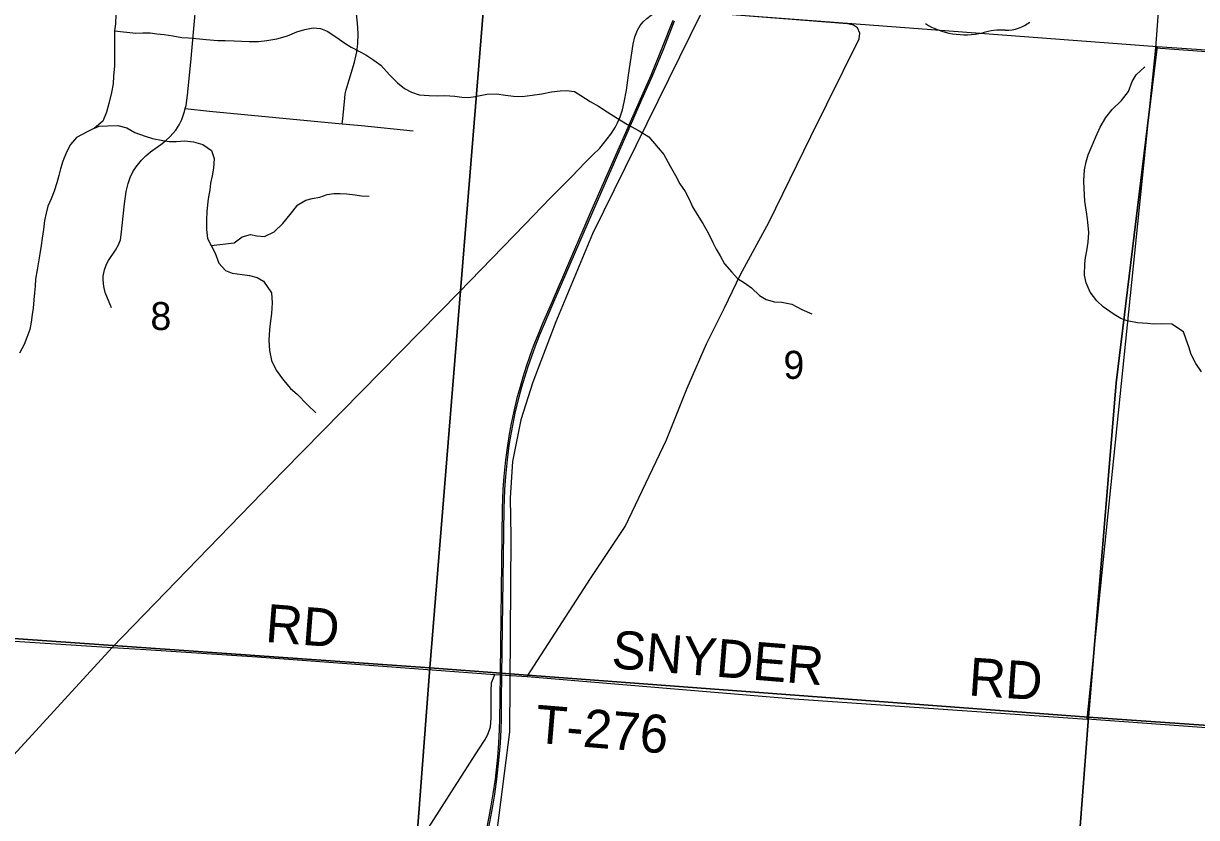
# Model space of a CAD drawing. Extents: x 0 to 42.5, y 0 to 22.
# Drawn here: x 2.796 to 3.672, y 14.84 to 15.433 of the extents above; entities that cross this region are included whole.
import ezdxf

# ---------------------------------------------------------------- set-up
doc = ezdxf.new("R2010")
doc.units = 0
for name, color, linetype in [('GM_X_County_Road', 7, 'Continuous'), ('GM_X_Minor_River', 7, 'Continuous'), ('GM_X_Rail_Line', 7, 'Continuous'), ('GM_X_Section', 7, 'Continuous'), ('GM_X_Section_Text', 7, 'Continuous'), ('GM_X_State_Route', 7, 'Continuous'), ('GM_X_State_Shield', 7, 'Continuous'), ('GM_X_Township_Road', 7, 'Continuous'), ('GM_X_Township_Road_Text', 7, 'Continuous')]:
    doc.layers.add(name, color=color, linetype=linetype)

msp = doc.modelspace()

# ---------------------------------------------------------------- linework, layer by layer
at = {"layer": 'GM_X_County_Road'}
msp.add_lwpolyline([(3.81125, 14.38966), (3.84476, 14.85241), (3.84714, 14.88263), (3.84662, 14.88758), (3.84418, 14.89065), (3.84154, 14.89333), (3.83908, 14.89469), (3.82959, 14.89592), (3.58977, 14.91333), (3.64105, 15.41464), (3.65438, 15.5918)], dxfattribs=at)
at = {"layer": 'GM_X_Minor_River'}
for points in [[(2.86473, 15.43941), (2.86453, 15.43257), (2.86376, 15.42744), (2.86371, 15.40122), (2.86313, 15.39343), (2.86274, 15.38773), (2.86159, 15.38127), (2.85968, 15.37311), (2.85796, 15.36665), (2.8551, 15.35982), (2.84882, 15.3547), (2.84388, 15.35204), (2.83533, 15.34769), (2.83095, 15.34238), (2.82791, 15.33668), (2.82524, 15.33004), (2.82352, 15.32434), (2.82218, 15.31921), (2.82084, 15.31389), (2.81874, 15.30763), (2.81645, 15.30174)], [(2.86376, 15.42744), (2.87971, 15.4257), (2.88484, 15.42588), (2.89053, 15.42587), (2.89547, 15.42511), (2.90078, 15.42453), (2.90724, 15.42357), (2.91407, 15.42241), (2.91901, 15.42203), (2.92737, 15.42125), (2.9323, 15.42086), (2.94085, 15.42009), (2.94654, 15.42008), (2.95319, 15.41988), (2.9587, 15.41949), (2.96439, 15.41929), (2.97123, 15.41947), (2.9775, 15.42003), (2.9851, 15.42134), (2.99289, 15.42361), (2.99992, 15.42664), (3.006, 15.42834), (3.01208, 15.42966), (3.01758, 15.42908), (3.02252, 15.42698), (3.02897, 15.42279), (3.03579, 15.41803), (3.04054, 15.41517), (3.04661, 15.41193), (3.05135, 15.40945), (3.05742, 15.40545), (3.06254, 15.40164), (3.06918, 15.39441), (3.07505, 15.38851), (3.08036, 15.38413), (3.08549, 15.38146), (3.09118, 15.37955), (3.09878, 15.37897), (3.10523, 15.37877), (3.11036, 15.37895), (3.11777, 15.37856), (3.12308, 15.37779), (3.12821, 15.37759), (3.13315, 15.37834), (3.1417, 15.38003), (3.14891, 15.38021), (3.15575, 15.37925), (3.16163, 15.37848), (3.16809, 15.37828), (3.17569, 15.37922), (3.1829, 15.38015), (3.19012, 15.38166), (3.19639, 15.3826), (3.20133, 15.38278), (3.20721, 15.38201), (3.21196, 15.37896), (3.21898, 15.37458), (3.22505, 15.37096), (3.23169, 15.36677), (3.23908, 15.36201), (3.24667, 15.35743), (3.2554, 15.35267), (3.26261, 15.3481), (3.26962, 15.33991), (3.27379, 15.33497), (3.27852, 15.32622), (3.2825, 15.31937), (3.28591, 15.3131), (3.2897, 15.30739), (3.29272, 15.30168), (3.29518, 15.29579), (3.29878, 15.29008), (3.30295, 15.28343), (3.30693, 15.27639), (3.31052, 15.26916), (3.31298, 15.26422), (3.31582, 15.25927), (3.31904, 15.25319), (3.32454, 15.2471), (3.3289, 15.24234), (3.33402, 15.2391), (3.33933, 15.23529), (3.34521, 15.22977), (3.35033, 15.22672), (3.3564, 15.22481), (3.36191, 15.2248), (3.36931, 15.22308), (3.3769, 15.21927), (3.3843, 15.21602)], [(3.62348, 15.38945), (3.62653, 15.39458), (3.633, 15.40046)], [(3.67515, 15.17257), (3.67099, 15.17885), (3.66739, 15.18551), (3.66569, 15.1914), (3.6638, 15.19672), (3.66172, 15.20262), (3.65318, 15.20814), (3.64559, 15.20854), (3.6397, 15.20836), (3.63496, 15.20875), (3.62736, 15.20914), (3.61977, 15.21067), (3.61502, 15.21258), (3.61009, 15.21544), (3.60193, 15.22115), (3.59719, 15.22572), (3.59208, 15.23219), (3.58924, 15.23903), (3.58792, 15.24474), (3.58813, 15.25329), (3.5887, 15.25804), (3.58966, 15.26297), (3.59062, 15.26943), (3.5912, 15.27665), (3.59027, 15.28444), (3.58952, 15.29052), (3.58801, 15.30022), (3.58765, 15.30953), (3.58747, 15.31523), (3.58786, 15.3234), (3.5892, 15.32947), (3.59073, 15.3346), (3.59283, 15.33992), (3.59626, 15.34827), (3.5995, 15.35549), (3.60369, 15.3627), (3.60864, 15.36858), (3.61548, 15.37541), (3.62062, 15.38205), (3.62348, 15.38945)], [(2.84882, 15.3547), (2.85225, 15.35621), (2.85851, 15.35639), (2.8663, 15.35657), (2.87313, 15.35485), (2.87901, 15.35142), (2.88661, 15.34874), (2.8923, 15.34683), (2.89989, 15.34549), (2.90483, 15.34472), (2.90977, 15.34471), (2.91641, 15.34508), (2.92268, 15.34431), (2.9297, 15.3424), (2.93615, 15.33783), (2.93823, 15.33193), (2.93765, 15.32471), (2.93669, 15.31902), (2.93554, 15.31351), (2.93496, 15.30857), (2.93362, 15.30173), (2.93266, 15.29261), (2.93246, 15.28577), (2.93245, 15.27894), (2.93319, 15.27228), (2.93603, 15.26696), (2.93887, 15.26125), (2.94171, 15.25384), (2.94664, 15.24832), (2.95176, 15.24641), (2.95917, 15.24526), (2.96448, 15.24468), (2.97037, 15.24315), (2.97511, 15.24029), (2.98098, 15.23173), (2.98154, 15.22413), (2.98096, 15.21615), (2.97999, 15.20874), (2.97942, 15.204), (2.97902, 15.19621), (2.97958, 15.1886), (2.98109, 15.18119), (2.98449, 15.17397), (2.98999, 15.16655), (2.9953, 15.16008), (3.00023, 15.15589), (3.008, 15.1479), (3.01407, 15.142)], [(2.81645, 15.30174), (2.81417, 15.29643), (2.81283, 15.29111), (2.81168, 15.28579), (2.81072, 15.27895), (2.80976, 15.2725), (2.80899, 15.26699), (2.80803, 15.26072), (2.80707, 15.25483), (2.80611, 15.24875), (2.80496, 15.24191), (2.80457, 15.23659), (2.80418, 15.23166), (2.8036, 15.22634), (2.80302, 15.22026), (2.80226, 15.21551), (2.80168, 15.20962), (2.80053, 15.2043), (2.79843, 15.19823), (2.79633, 15.1931), (2.7929, 15.18665)], [(2.93603, 15.26696), (2.95313, 15.26902), (2.95902, 15.27357), (2.96529, 15.27527), (2.97004, 15.27431), (2.97573, 15.27373), (2.98296, 15.27714), (2.98942, 15.2834), (2.99494, 15.29023), (3.00065, 15.29744), (3.00673, 15.30085), (3.01148, 15.30198), (3.01699, 15.30311), (3.0225, 15.305), (3.02744, 15.30575), (3.03219, 15.30593), (3.03712, 15.30555), (3.04339, 15.30496), (3.04814, 15.3042), (3.05383, 15.30381)]]:
    msp.add_lwpolyline(points, dxfattribs=at)
at = {"layer": 'GM_X_Rail_Line'}
for points in [[(3.47328, 15.92052), (3.46744, 15.82178), (3.46367, 15.75338), (3.44096, 15.69989), (3.43137, 15.67586), (3.41647, 15.65133), (3.3017, 15.44053), (3.22062, 15.27562), (3.19329, 15.2099), (3.17616, 15.16485), (3.16703, 15.1369), (3.161, 15.10576), (3.15922, 15.07853), (3.15956, 15.04953), (3.15856, 14.90389), (3.14925, 14.82993)], [(3.14195, 14.83262), (3.14349, 14.84043), (3.14503, 14.84859), (3.1465, 14.85754), (3.1481, 14.86856), (3.14988, 14.88491), (3.15063, 14.8954), (3.15118, 14.90554), (3.15138, 14.91343), (3.15161, 14.92814), (3.15338, 15.07069), (3.15386, 15.08489), (3.15462, 15.09455), (3.15586, 15.10703), (3.15731, 15.11772), (3.15869, 15.12621), (3.1602, 15.13413), (3.16179, 15.14199), (3.16469, 15.1542), (3.16676, 15.16165), (3.16889, 15.16903), (3.17138, 15.17689), (3.17413, 15.18482), (3.17689, 15.19247), (3.18, 15.20034), (3.18358, 15.20888), (3.18997, 15.22366), (3.21974, 15.29254), (3.25644, 15.3764), (3.26434, 15.39419), (3.27265, 15.41458), (3.28083, 15.4352)], [(3.14313, 14.83237), (3.14467, 14.84021), (3.14621, 14.84838), (3.14768, 14.85736), (3.14929, 14.86841), (3.15107, 14.88481), (3.15183, 14.89532), (3.15238, 14.9055), (3.15258, 14.9134), (3.15281, 14.92812), (3.15458, 15.07067), (3.15506, 15.08483), (3.15581, 15.09445), (3.15705, 15.10689), (3.1585, 15.11754), (3.15987, 15.126), (3.16138, 15.1339), (3.16296, 15.14174), (3.16585, 15.1539), (3.16791, 15.16133), (3.17004, 15.16868), (3.17252, 15.17652), (3.17527, 15.18442), (3.17802, 15.19205), (3.18111, 15.19989), (3.18468, 15.20841), (3.19108, 15.22319), (3.22084, 15.29206), (3.25754, 15.37592), (3.26545, 15.39372), (3.27376, 15.41413), (3.28194, 15.43475)]]:
    msp.add_lwpolyline(points, dxfattribs=at)
at = {"layer": 'GM_X_Section'}
for points in [[(2.62095, 15.50275), (3.14004, 15.45367), (3.09918, 14.95159), (2.58723, 14.98757)], [(3.14004, 15.45367), (3.64215, 15.41565), (3.61158, 15.16447), (3.59088, 14.91475), (3.09918, 14.95159)], [(3.64215, 15.41565), (4.14371, 15.38143), (4.10606, 14.87895), (3.59088, 14.91475), (3.61158, 15.16447)], [(2.58723, 14.98757), (3.09918, 14.95159), (3.06197, 14.45953), (2.55405, 14.50856)], [(3.09918, 14.95159), (3.59088, 14.91475), (3.55348, 14.42497), (3.06197, 14.45953)], [(3.59088, 14.91475), (4.10606, 14.87895), (4.07019, 14.38934), (3.55348, 14.42497)]]:
    msp.add_lwpolyline(points, close=True, dxfattribs=at)
at = {"layer": 'GM_X_State_Route'}
for points in [[(3.22092, 15.33472), (3.22599, 15.33968), (3.23429, 15.35011), (3.23748, 15.35522), (3.23929, 15.35873), (3.24132, 15.3631), (3.24291, 15.36821), (3.2443, 15.37406), (3.24589, 15.38289), (3.24749, 15.39418), (3.251, 15.41738), (3.25217, 15.42291), (3.25409, 15.4277), (3.25632, 15.43121), (3.25835, 15.43409), (3.26111, 15.43643), (3.26452, 15.43898), (3.26899, 15.4409), (3.27261, 15.44218), (3.27814, 15.44292), (3.28841, 15.44205)], [(2.56033, 14.46219), (2.57653, 14.50438), (2.62421, 14.627), (2.64847, 14.69299), (2.66039, 14.72449), (2.66848, 14.74237), (2.677, 14.75812), (2.68679, 14.7743), (2.69701, 14.78707), (2.73703, 14.83007), (2.77747, 14.87477), (2.86219, 14.96673), (2.98992, 15.09871), (3.12083, 15.23197), (3.14574, 15.25751), (3.17, 15.28263), (3.18938, 15.30264), (3.20513, 15.31861), (3.21513, 15.32904), (3.22092, 15.33472)]]:
    msp.add_lwpolyline(points, dxfattribs=at)
at = {"layer": 'GM_X_State_Shield'}
for centre, major_axis, start_param, end_param in [((3.49877, 15.46185), (0.04687, 0), 4.026481, 4.996735), ((3.52927, 15.44783), (0.02497, 0), 4.691044, 5.507374), ((3.52585, 15.39714), (0.03851, 0), 1.495662, 1.94098)]:
    msp.add_ellipse(centre, major_axis=major_axis, ratio=0.8, start_param=start_param, end_param=end_param, dxfattribs=at)
at = {"layer": 'GM_X_Township_Road'}
msp.add_line((3.14767, 14.94663), (3.1718, 14.94504), dxfattribs=at)
for points in [[(3.03382, 15.35787), (3.03419, 15.3617), (3.03566, 15.37713), (3.03609, 15.3803), (3.03674, 15.38323), (3.03886, 15.39067), (3.04303, 15.40399), (3.04476, 15.41154), (3.04547, 15.4177), (3.04567, 15.42544), (3.04511, 15.43316), (3.04413, 15.44234), (3.04394, 15.44859), (3.04413, 15.45393), (3.04511, 15.46217)], [(2.86161, 15.22045), (2.85971, 15.2247), (2.85691, 15.23194), (2.85573, 15.23644), (2.85525, 15.24106), (2.85537, 15.24416), (2.85623, 15.24874), (2.85782, 15.2531), (2.85927, 15.25584), (2.86457, 15.26351), (2.8668, 15.26758), (2.8683, 15.27132), (2.86889, 15.27501), (2.87126, 15.29812), (2.87246, 15.30733), (2.87397, 15.31334), (2.87553, 15.31772), (2.87758, 15.3219), (2.88004, 15.32586), (2.88386, 15.33075), (2.88712, 15.33407), (2.89069, 15.33706), (2.89831, 15.34243), (2.90198, 15.34529), (2.90537, 15.34848), (2.90948, 15.35314), (2.91209, 15.357), (2.91414, 15.36118), (2.91613, 15.36706), (2.91664, 15.36927), (2.91719, 15.37159), (2.91829, 15.37928), (2.92068, 15.40401), (2.92461, 15.44576)], [(3.1718, 14.94504), (3.21901, 15.01819), (3.24494, 15.0572), (3.27596, 15.12191), (3.2912, 15.16034), (3.30581, 15.19368), (3.31914, 15.22035), (3.33121, 15.24544), (3.35217, 15.28418), (3.38369, 15.34846), (3.41969, 15.42143), (3.42005, 15.42565), (3.4184, 15.42968), (3.41547, 15.43151), (3.41089, 15.43261), (3.32808, 15.43902), (3.32433, 15.4425)], [(3.64105, 15.41464), (3.93354, 15.39352), (4.20865, 15.37279)], [(2.91664, 15.36927), (2.93483, 15.36724), (3.03382, 15.35787), (3.04807, 15.35652), (3.08683, 15.35265)], [(2.58535, 14.98458), (2.86219, 14.96673), (2.88723, 14.96516)], [(2.88723, 14.96516), (2.97033, 14.95992), (3.14767, 14.94663)], [(3.0867, 14.81405), (3.13311, 14.88669), (3.14005, 14.89725), (3.14259, 14.90169), (3.14449, 14.90757), (3.14497, 14.91392), (3.14497, 14.93425), (3.14529, 14.94044), (3.14767, 14.94663)], [(3.1718, 14.94504), (3.37109, 14.92845), (3.58977, 14.91333)]]:
    msp.add_lwpolyline(points, dxfattribs=at)

# ---------------------------------------------------------------- texts
at = {"layer": 'GM_X_Section_Text'}
for s, p in [('8', (2.89064, 15.20386)), ('9', (3.36314, 15.1674))]:
    msp.add_text(s, height=0.02093, rotation=0.00001, dxfattribs=at).set_placement(p)
at = {"layer": 'GM_X_Township_Road_Text'}
for s, rotation, p in [('RD', 355.52558, (2.97589, 14.97101)), ('SNYDER', 355.3366, (3.23426, 14.95143)), ('RD', 356.05326, (3.50078, 14.93102)), ('T-276', 355.21346, (3.17715, 14.89574))]:
    msp.add_text(s, height=0.028409, rotation=rotation, dxfattribs=at).set_placement(p)

doc.saveas('drawing.dxf')
